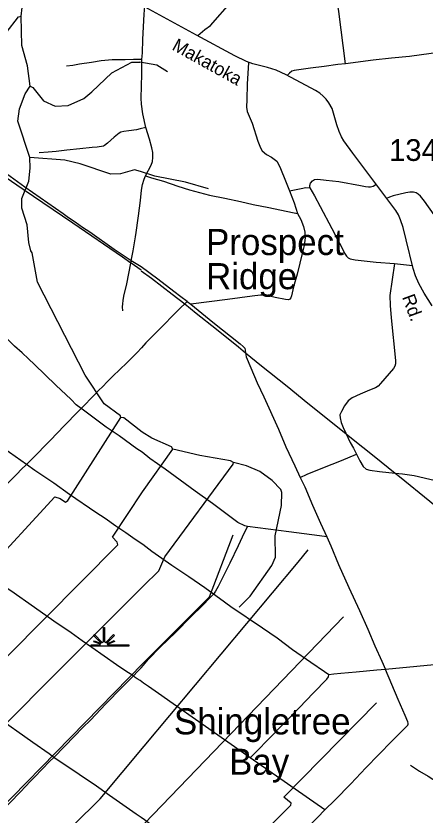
# Model space of a CAD drawing. Extents: x 2104537 to 2336408, y 34176 to 229611.
# Drawn here: x 2186502 to 2195903, y 104935 to 123300 of the extents above; entities that cross this region are included whole.
import ezdxf

# ---------------------------------------------------------------- set-up
doc = ezdxf.new("R2010")
doc.units = 0
for name, color, linetype in [('Exist Hydrographic Creek Single Shore', 7, 'Continuous'), ('Exist Hydrographic Misc Water Feature', 7, 'Continuous'), ('Exist Hydrographic Point Label', 7, 'Continuous'), ('Exist Hydrographic Swamp CELL', 7, 'Continuous'), ('Exist Road Non-System Type 51', 7, 'Continuous'), ('Exist Road Secondary Type 51 Attributed', 7, 'Continuous'), ('Exist Road Secondary Type 51 Label', 7, 'Continuous'), ('Exist Road Secondary Type 51 Number Label', 7, 'Continuous'), ('Exist Utilities Electrical Transmission Line', 7, 'Continuous')]:
    doc.layers.add(name, color=color, linetype=linetype)

msp = doc.modelspace()

# ---------------------------------------------------------------- linework, layer by layer
at = {"layer": 'Exist Hydrographic Creek Single Shore'}
msp.add_lwpolyline([(2186618, 123297), (2186642, 123496)], dxfattribs=at)
at = {"layer": 'Exist Hydrographic Misc Water Feature'}
for p, q in [((2189408, 112363), (2190106, 113344)), ((2192990, 110749), (2193221, 111027)), ((2189445, 106517), (2192990, 110749)), ((2189456, 104742), (2194031, 109489)), ((2183628, 102499), (2189433, 108434))]:
    msp.add_line(p, q, dxfattribs=at)
for points in [[(2176295, 113041), (2176626, 113274), (2177148, 113887), (2179477, 116008), (2180174, 116552), (2180182, 116594), (2180315, 116713), (2180522, 116981), (2180894, 117315), (2181334, 117792), (2181997, 118255), (2182378, 118658), (2182851, 119026), (2183579, 119937), (2184053, 120233), (2184741, 120804), (2185633, 122158), (2185691, 122183), (2186097, 122559), (2186213, 122737), (2186279, 122913), (2186560, 123278), (2186618, 123297)], [(2186827, 121688), (2186766, 122155), (2186639, 122620), (2186618, 123297)], [(2186827, 121688), (2186886, 121658), (2187137, 121351), (2187404, 121228), (2187704, 121245), (2188062, 121405), (2188244, 121556), (2188708, 121993), (2189165, 122237), (2189346, 122240)], [(2189988, 122017), (2189737, 122173), (2189346, 122240)], [(2186820, 120048), (2186548, 120880), (2186580, 121165), (2186711, 121513), (2186827, 121688)], [(2188911, 114070), (2188903, 114112), (2188526, 114385), (2188089, 115047), (2186994, 117184), (2186874, 117859), (2186840, 117899), (2186797, 118090), (2186762, 118497), (2186634, 118881), (2186633, 119107), (2186798, 119507), (2186829, 119799), (2186820, 120048)], [(2189362, 119723), (2189229, 119762), (2188905, 119670), (2188680, 119668), (2187978, 119904), (2187628, 119987), (2186820, 120048)], [(2190923, 119326), (2190397, 119480), (2189696, 119615), (2189362, 119723)], [(2180357, 104816), (2184169, 108335), (2184160, 108535), (2184126, 108693), (2187397, 112245), (2187514, 112213), (2187639, 112129), (2187697, 112164), (2188911, 114070)], [(2189400, 113735), (2188978, 114062), (2188911, 114070)], [(2190106, 113344), (2190080, 113394), (2189621, 113600), (2189400, 113735)], [(2191499, 113038), (2191432, 113079), (2190731, 113201), (2190106, 113344)], [(2189422, 110194), (2189783, 110546), (2189923, 110871), (2191491, 112996), (2191499, 113038)], [(2191631, 109716), (2191887, 109967), (2192382, 110669), (2192464, 110861), (2192460, 111353), (2192606, 112046), (2192612, 112348), (2192587, 112414), (2192393, 112627), (2192110, 112827), (2191800, 112957), (2191499, 113038)], [(2181419, 104044), (2185297, 107785), (2185406, 107710), (2185464, 107742), (2188844, 111144), (2188827, 111204), (2188718, 111321), (2189408, 112363)], [(2189433, 108434), (2190946, 109952), (2191494, 111372)], [(2182565, 103261), (2184205, 104978), (2189422, 110194)], [(2189474, 101834), (2192820, 105159), (2192828, 105208), (2192660, 105349), (2194786, 107512)], [(2184782, 101706), (2188436, 105309), (2189445, 106517)]]:
    msp.add_lwpolyline(points, dxfattribs=at)
at = {"layer": 'Exist Hydrographic Swamp CELL'}
msp.add_lwpolyline([(2188227, 108843), (2188438, 108843), (2188446, 108858), (2188293, 108917), (2188304, 108938), (2188455, 108875), (2188462, 108886), (2188284, 109064), (2188304, 109085), (2188486, 108903), (2188511, 108913), (2188511, 109245), (2188540, 109245), (2188540, 108913), (2188565, 108903), (2188746, 109085), (2188767, 109064), (2188589, 108886), (2188597, 108872), (2188761, 108946), (2188770, 108926), (2188607, 108855), (2188613, 108843), (2189097, 108843), (2189097, 108814), (2188227, 108814)], close=True, dxfattribs=at)
at = {"layer": 'Exist Road Non-System Type 51'}
for p, q in [((2189140, 117620), (2189151, 117675)), ((2195203, 117611), (2195617, 117567)), ((2190439, 116740), (2190380, 116683)), ((2190439, 116740), (2190521, 116678)), ((2193602, 105054), (2191887, 106247))]:
    msp.add_line(p, q, dxfattribs=at)
for points in [[(2194076, 122203), (2193919, 123404), (2193854, 123859), (2193800, 124306), (2193739, 124754), (2193694, 125141), (2193584, 125946), (2193522, 126381), (2193467, 126821), (2193314, 127949), (2193234, 128588)], [(2190681, 122853), (2190842, 122992), (2190975, 123080), (2191474, 123652), (2191735, 123947), (2192006, 124239), (2192275, 124536)], [(2189396, 122303), (2189409, 122453), (2189420, 122759), (2189449, 123339), (2189463, 123529)], [(2189151, 117675), (2188761, 117930), (2188196, 118329), (2188030, 118439), (2187864, 118558), (2187707, 118662), (2187589, 118750), (2186709, 119362), (2186108, 119791), (2185890, 119939), (2185814, 119987), (2185698, 120052), (2185508, 120192), (2185127, 120459), (2184831, 120665), (2184713, 120740), (2184298, 121028), (2183982, 121251), (2183073, 121871), (2182911, 121987), (2182188, 122487), (2182094, 122549), (2181966, 122641)], [(2196719, 122513), (2196508, 122485), (2196048, 122434), (2195544, 122371), (2195129, 122329), (2194711, 122281), (2194076, 122203)], [(2189396, 122303), (2189346, 122298), (2189201, 122301), (2189011, 122294), (2188714, 122296), (2188463, 122269), (2188241, 122231), (2187961, 122192), (2187805, 122164), (2187661, 122144)], [(2189484, 120734), (2189419, 121049), (2189385, 121273), (2189379, 121413), (2189392, 121959), (2189391, 122091), (2189396, 122303)], [(2191843, 122234), (2191818, 121736), (2191806, 121380), (2191803, 121208), (2191817, 121101), (2191927, 120835), (2192061, 120424), (2192119, 120269), (2192161, 120197), (2192256, 120116), (2192373, 120056), (2192439, 120012), (2192500, 119961), (2192567, 119831), (2192713, 119475), (2192786, 119284)], [(2194076, 122203), (2193896, 122186), (2193587, 122137), (2193273, 122102), (2192898, 122048), (2192844, 122030), (2192790, 121989), (2192739, 121939)], [(2189484, 120734), (2189356, 120705), (2189269, 120683), (2189097, 120657), (2188980, 120642), (2188910, 120626), (2188872, 120604), (2188834, 120578), (2188758, 120514), (2188684, 120446), (2188602, 120376), (2188540, 120326), (2188514, 120310), (2188370, 120287), (2188250, 120277), (2187971, 120243), (2187667, 120216), (2187427, 120189), (2187239, 120173), (2187037, 120151)], [(2189482, 119628), (2189608, 119869), (2189636, 119959), (2189646, 120051), (2189649, 120159), (2189628, 120269), (2189570, 120470), (2189484, 120734)], [(2189151, 117675), (2189196, 117901), (2189210, 117997), (2189252, 118225), (2189262, 118321), (2189311, 118655), (2189315, 118709), (2189366, 119062), (2189388, 119293), (2189413, 119425), (2189445, 119546), (2189482, 119628)], [(2189482, 119628), (2189619, 119581), (2189896, 119500), (2190221, 119389), (2190492, 119308), (2190951, 119180), (2191300, 119113), (2191659, 119037), (2191957, 118968), (2192310, 118901), (2192855, 118784), (2192975, 118762)], [(2193256, 119350), (2193253, 119402), (2193273, 119455), (2193318, 119513), (2193366, 119541), (2193436, 119548), (2193632, 119530), (2193924, 119494), (2194421, 119407), (2194537, 119378), (2194604, 119373), (2194650, 119375), (2194711, 119388), (2194773, 119428)], [(2192786, 119284), (2193092, 119346), (2193155, 119357), (2193256, 119350)], [(2192786, 119284), (2192893, 119003), (2192975, 118762)], [(2193256, 119350), (2193361, 119169), (2193490, 118918), (2193765, 118419), (2193883, 118180), (2193983, 117995), (2194054, 117852), (2194097, 117776), (2194133, 117745), (2194186, 117715), (2194300, 117694), (2194784, 117641), (2195203, 117611)], [(2196509, 117221), (2196566, 117304), (2196595, 117392), (2196604, 117465), (2196583, 117560), (2196339, 118224), (2196218, 118528), (2196116, 118730), (2195889, 119047), (2195800, 119156), (2195746, 119205), (2195699, 119233), (2195641, 119250), (2195557, 119250), (2195464, 119235), (2195168, 119164), (2195084, 119136), (2195014, 119105)], [(2192975, 118762), (2193045, 118622), (2193108, 118463), (2193142, 118333), (2193147, 118203), (2193122, 118025), (2193080, 117841), (2193022, 117616), (2192965, 117363), (2192884, 117077), (2192834, 116868), (2192818, 116822), (2192799, 116794), (2192762, 116779), (2192700, 116783), (2192456, 116833), (2192330, 116864), (2192225, 116880), (2192123, 116882), (2191928, 116862), (2191366, 116786), (2190521, 116678)], [(2188957, 116523), (2188949, 116615), (2188955, 116683), (2188967, 116761), (2188984, 116863), (2189046, 117141), (2189140, 117620)], [(2190439, 116740), (2190290, 116846), (2190128, 116968), (2189763, 117251), (2189376, 117531), (2189151, 117675)], [(2195203, 117611), (2195096, 116872), (2195100, 116644), (2195123, 116360), (2195222, 115378), (2195223, 115307), (2195209, 115253), (2195176, 115199), (2194883, 114850), (2194824, 114788), (2194768, 114753), (2194629, 114700), (2194414, 114610), (2194232, 114526), (2194135, 114455), (2194050, 114338), (2193980, 114212), (2193948, 114131), (2193951, 114062), (2193978, 113954), (2194019, 113842), (2194084, 113713), (2194092, 113696)], [(2187997, 114281), (2187885, 114365), (2187767, 114485), (2187421, 114812), (2186930, 115289), (2186786, 115423), (2186648, 115557), (2186471, 115714), (2186077, 116101), (2185436, 116714), (2185197, 116950), (2185121, 117012)], [(2190380, 116683), (2190294, 116600), (2189719, 116021), (2189485, 115791), (2189387, 115675), (2189289, 115567), (2189049, 115329), (2188730, 115024), (2188598, 114892), (2188498, 114786), (2188396, 114690), (2188309, 114594), (2188221, 114508), (2188093, 114371), (2187997, 114281)], [(2190521, 116678), (2190687, 116538), (2191027, 116259), (2191652, 115763), (2191721, 115704), (2191758, 115663), (2191772, 115617), (2191779, 115561)], [(2186742, 112991), (2186083, 113450), (2185683, 113735), (2184650, 114455), (2184222, 114748), (2183373, 115339), (2183147, 115492), (2182840, 115711), (2182524, 115923), (2182458, 115971), (2182378, 116037)], [(2191779, 115561), (2191791, 115464), (2191898, 115210), (2192049, 114869), (2192200, 114547), (2192535, 113802), (2192707, 113400), (2192908, 112964), (2193034, 112695)], [(2186742, 112991), (2186872, 113125), (2187287, 113540), (2187614, 113890), (2187926, 114203), (2187997, 114281)], [(2191825, 111568), (2191759, 111585), (2191602, 111659), (2191018, 112096), (2190623, 112378), (2189934, 112883), (2189582, 113132), (2189403, 113271), (2189281, 113352), (2188876, 113649), (2188574, 113852), (2188146, 114172), (2188053, 114237), (2187997, 114281)], [(2194092, 113696), (2194186, 113500), (2194260, 113364), (2194325, 113225)], [(2193034, 112695), (2193197, 112767), (2193554, 112912), (2193985, 113082), (2194325, 113225)], [(2194325, 113225), (2194402, 113076), (2194484, 112943), (2194552, 112885), (2194636, 112860), (2194857, 112828), (2195216, 112792)], [(2184888, 111112), (2185373, 111607), (2185521, 111753), (2186036, 112280), (2186145, 112384), (2186257, 112502), (2186531, 112777), (2186622, 112873), (2186742, 112991)], [(2191038, 110010), (2190840, 110154), (2190474, 110407), (2190087, 110667), (2189628, 110989), (2189416, 111153), (2189241, 111264), (2189026, 111419), (2188798, 111571), (2188548, 111747), (2188336, 111886), (2187729, 112305), (2187369, 112560), (2186934, 112853), (2186742, 112991)], [(2195216, 112792), (2195385, 112775), (2195656, 112738), (2196372, 112569)], [(2193034, 112695), (2193142, 112476), (2193316, 112056), (2193500, 111642), (2193643, 111331)], [(2191825, 111568), (2191748, 111423), (2191609, 111124), (2191419, 110724), (2191150, 110185), (2191087, 110079), (2191038, 110010)], [(2193643, 111331), (2193479, 111350), (2192776, 111446), (2191825, 111568)], [(2193643, 111331), (2193738, 111120), (2193918, 110694), (2194149, 110168), (2194394, 109636), (2194588, 109204), (2194748, 108822), (2194913, 108468), (2194995, 108282)], [(2189202, 108134), (2189052, 108228), (2188816, 108389), (2188247, 108788), (2188021, 108942), (2187767, 109119), (2187370, 109389), (2186926, 109706), (2186381, 110089), (2186169, 110226), (2185723, 110531), (2185511, 110679), (2185329, 110811), (2184888, 111112)], [(2189202, 108134), (2189294, 108232), (2189382, 108320), (2189435, 108381), (2189550, 108520), (2189819, 108793), (2190170, 109132), (2190527, 109495), (2190786, 109752), (2190965, 109938), (2191038, 110010)], [(2193692, 108154), (2193589, 108229), (2193275, 108442), (2192856, 108734), (2192502, 108996), (2192164, 109231), (2191442, 109722), (2191179, 109908), (2191038, 110010)], [(2187372, 106259), (2187262, 106339), (2186886, 106598), (2186015, 107214), (2185773, 107374), (2185288, 107725), (2185066, 107878), (2184503, 108259), (2184007, 108620), (2183654, 108864), (2183472, 108983), (2183172, 109193), (2183070, 109273)], [(2197877, 108542), (2197585, 108515), (2196998, 108468), (2194995, 108282)], [(2193602, 105054), (2193834, 105280), (2194197, 105649), (2194541, 106017), (2195141, 106634), (2195506, 107001), (2195518, 107023), (2195517, 107049), (2195509, 107074), (2195447, 107225), (2195286, 107591), (2194995, 108282)], [(2194995, 108282), (2194797, 108267), (2194324, 108218), (2193966, 108184), (2193810, 108173), (2193692, 108154)], [(2187372, 106259), (2187857, 106756), (2188031, 106938), (2188220, 107126), (2188557, 107479), (2188945, 107870), (2189017, 107948), (2189202, 108134)], [(2191887, 106247), (2190114, 107492), (2189774, 107725), (2189544, 107886), (2189435, 107968), (2189356, 108029), (2189284, 108068), (2189242, 108098), (2189202, 108134)], [(2191887, 106247), (2192011, 106380), (2192328, 106699), (2193013, 107402), (2193342, 107741), (2193643, 108057), (2193685, 108112), (2193692, 108154)], [(2185642, 104488), (2185750, 104602), (2185879, 104724), (2186606, 105471), (2186833, 105710), (2186931, 105806), (2187282, 106173), (2187372, 106259)], [(2191782, 103206), (2191603, 103339), (2191238, 103591), (2190396, 104173), (2189609, 104711), (2189456, 104826), (2189382, 104881), (2189266, 104958), (2188649, 105385), (2188299, 105635), (2188123, 105750), (2187783, 105982), (2187470, 106189), (2187372, 106259)], [(2195569, 106079), (2195773, 105943), (2195977, 105825), (2196082, 105757), (2196181, 105646), (2196311, 105467), (2196465, 105213), (2196601, 105009), (2196737, 104675), (2196830, 104415), (2196997, 103982), (2197133, 103951), (2197312, 103883), (2197418, 103833), (2197566, 103784), (2197665, 103747), (2197745, 103716)], [(2191782, 103206), (2191944, 103380), (2192311, 103754), (2192725, 104171), (2193073, 104516), (2193432, 104876), (2193602, 105054)]]:
    msp.add_lwpolyline(points, dxfattribs=at)
at = {"layer": 'Exist Road Secondary Type 51 Attributed'}
msp.add_lwpolyline([(2196068, 116639), (2195881, 116933), (2195761, 117152), (2195682, 117329), (2195629, 117499), (2195467, 118153), (2195403, 118436), (2195342, 118617), (2195290, 118730), (2195234, 118832), (2195141, 118949), (2194245, 120149), (2194037, 120432), (2193980, 120525), (2193928, 120645), (2193874, 120796), (2193799, 121068), (2193768, 121174), (2193693, 121301), (2193634, 121385), (2193562, 121460), (2193482, 121527), (2193387, 121586), (2192709, 121948), (2192480, 122055), (2192279, 122118), (2191946, 122197), (2191799, 122254), (2191530, 122385), (2190652, 122858), (2189137, 123696)], dxfattribs=at)
at = {"layer": 'Exist Utilities Electrical Transmission Line'}
for points in [[(2189140, 117620), (2188947, 117759), (2187805, 118538), (2186670, 119311), (2184763, 120612), (2183627, 121401), (2181699, 122736)], [(2189377, 117461), (2189146, 117616), (2189140, 117620)], [(2189376, 117439), (2189613, 117274), (2190095, 116910), (2190380, 116683)], [(2190380, 116683), (2190643, 116473), (2191111, 116098), (2191617, 115693), (2191779, 115561)], [(2191779, 115561), (2192147, 115262), (2192733, 114790), (2193211, 114404), (2193622, 114074), (2194092, 113696)], [(2194092, 113696), (2194217, 113596), (2194731, 113183), (2195216, 112792)], [(2195216, 112792), (2195315, 112713), (2196017, 112145), (2196513, 111738), (2197047, 111297), (2197568, 110872), (2198126, 110420), (2198612, 110027), (2199204, 109548), (2199680, 109161), (2200110, 108809), (2200678, 108347), (2201152, 107961), (2201632, 107572), (2202160, 107143), (2202351, 106987)]]:
    msp.add_lwpolyline(points, dxfattribs=at)

# ---------------------------------------------------------------- texts
at = {"layer": 'Exist Hydrographic Point Label'}
for s, p in [('Prospect', (2190870, 117805)), ('Ridge', (2190870, 117020)), ('Shingletree', (2190132, 106788)), ('Bay', (2191399, 105860))]:
    msp.add_text(s, height=600, dxfattribs=at).set_placement(p)
at = {"layer": 'Exist Road Secondary Type 51 Label'}
for s, rotation, p in [('Makatoka', 330.9398, (2190067, 122537)), ('Rd.', 290.226, (2195371, 116840))]:
    msp.add_text(s, height=300, rotation=rotation, dxfattribs=at).set_placement(p)
at = {"layer": 'Exist Road Secondary Type 51 Number Label'}
msp.add_text('1342', height=500, dxfattribs=at).set_placement((2195079, 119969))

doc.saveas('drawing.dxf')
